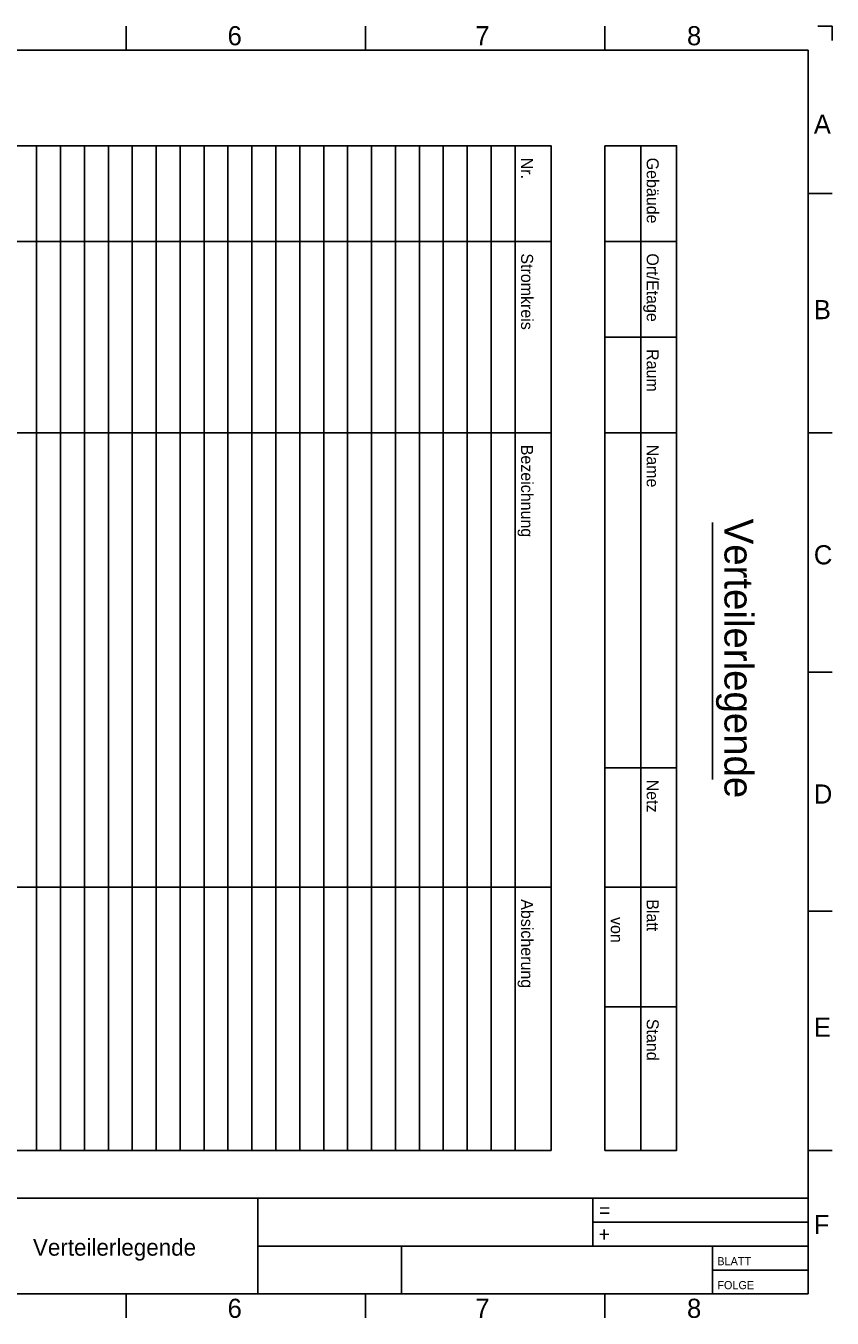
# Model space of a CAD drawing. Extents: x 0 to 395, y 0 to 270.
# Drawn here: x 226.5 to 395, y -0.1 to 270.1 of the extents above; entities that cross this region are included whole.
import ezdxf

# ---------------------------------------------------------------- set-up
doc = ezdxf.new("R2010")
doc.units = 0
for name, color, linetype in [('30_Graphik', 7, 'Continuous'), ('30_Text', 7, 'Continuous'), ('90_Plankopf', 7, 'Continuous')]:
    doc.layers.add(name, color=color, linetype=linetype)

msp = doc.modelspace()

# ---------------------------------------------------------------- linework, layer by layer
at = {"layer": '30_Graphik'}
msp.add_line((370, 166.25), (370, 112.5), dxfattribs=at)
for points in [[(223.75, 245), (223.75, 225), (228.75, 225), (228.75, 245)], [(228.75, 245), (228.75, 225), (233.75, 225), (233.75, 245)], [(233.75, 245), (233.75, 225), (238.75, 225), (238.75, 245)], [(238.75, 245), (238.75, 225), (243.75, 225), (243.75, 245)], [(243.75, 245), (243.75, 225), (248.75, 225), (248.75, 245)], [(248.75, 245), (248.75, 225), (253.75, 225), (253.75, 245)], [(253.75, 245), (253.75, 225), (258.75, 225), (258.75, 245)], [(258.75, 245), (258.75, 225), (263.75, 225), (263.75, 245)], [(263.75, 245), (263.75, 225), (268.75, 225), (268.75, 245)], [(268.75, 245), (268.75, 225), (273.75, 225), (273.75, 245)], [(273.75, 245), (273.75, 225), (278.75, 225), (278.75, 245)], [(278.75, 245), (278.75, 225), (283.75, 225), (283.75, 245)], [(283.75, 245), (283.75, 225), (288.75, 225), (288.75, 245)], [(288.75, 245), (288.75, 225), (293.75, 225), (293.75, 245)], [(293.75, 245), (293.75, 225), (298.75, 225), (298.75, 245)], [(298.75, 245), (298.75, 225), (303.75, 225), (303.75, 245)], [(303.75, 245), (303.75, 225), (308.75, 225), (308.75, 245)], [(308.75, 245), (308.75, 225), (313.75, 225), (313.75, 245)], [(313.75, 245), (313.75, 225), (318.75, 225), (318.75, 245)], [(318.75, 245), (318.75, 225), (323.75, 225), (323.75, 245)], [(323.75, 245), (323.75, 225), (328.75, 225), (328.75, 245)], [(328.75, 245), (328.75, 225), (336.25, 225), (336.25, 245)], [(347.5, 245), (347.5, 225), (355, 225), (355, 245)], [(355, 245), (355, 225), (362.5, 225), (362.5, 245)], [(223.75, 225), (223.75, 185), (228.75, 185), (228.75, 225)], [(228.75, 225), (228.75, 185), (233.75, 185), (233.75, 225)], [(233.75, 225), (233.75, 185), (238.75, 185), (238.75, 225)], [(238.75, 225), (238.75, 185), (243.75, 185), (243.75, 225)], [(243.75, 225), (243.75, 185), (248.75, 185), (248.75, 225)], [(248.75, 225), (248.75, 185), (253.75, 185), (253.75, 225)], [(253.75, 225), (253.75, 185), (258.75, 185), (258.75, 225)], [(258.75, 225), (258.75, 185), (263.75, 185), (263.75, 225)], [(263.75, 225), (263.75, 185), (268.75, 185), (268.75, 225)], [(268.75, 225), (268.75, 185), (273.75, 185), (273.75, 225)], [(273.75, 225), (273.75, 185), (278.75, 185), (278.75, 225)], [(278.75, 225), (278.75, 185), (283.75, 185), (283.75, 225)], [(283.75, 225), (283.75, 185), (288.75, 185), (288.75, 225)], [(288.75, 225), (288.75, 185), (293.75, 185), (293.75, 225)], [(293.75, 225), (293.75, 185), (298.75, 185), (298.75, 225)], [(298.75, 225), (298.75, 185), (303.75, 185), (303.75, 225)], [(303.75, 225), (303.75, 185), (308.75, 185), (308.75, 225)], [(308.75, 225), (308.75, 185), (313.75, 185), (313.75, 225)], [(313.75, 225), (313.75, 185), (318.75, 185), (318.75, 225)], [(318.75, 225), (318.75, 185), (323.75, 185), (323.75, 225)], [(323.75, 225), (323.75, 185), (328.75, 185), (328.75, 225)], [(328.75, 225), (328.75, 185), (336.25, 185), (336.25, 225)], [(347.5, 225), (347.5, 205), (355, 205), (355, 225)], [(355, 225), (355, 205), (362.5, 205), (362.5, 225)], [(347.5, 205), (347.5, 185), (355, 185), (355, 205)], [(355, 205), (355, 185), (362.5, 185), (362.5, 205)], [(223.75, 185), (223.75, 90), (228.75, 90), (228.75, 185)], [(228.75, 185), (228.75, 90), (233.75, 90), (233.75, 185)], [(233.75, 185), (233.75, 90), (238.75, 90), (238.75, 185)], [(238.75, 185), (238.75, 90), (243.75, 90), (243.75, 185)], [(243.75, 185), (243.75, 90), (248.75, 90), (248.75, 185)], [(248.75, 185), (248.75, 90), (253.75, 90), (253.75, 185)], [(253.75, 185), (253.75, 90), (258.75, 90), (258.75, 185)], [(258.75, 185), (258.75, 90), (263.75, 90), (263.75, 185)], [(263.75, 185), (263.75, 90), (268.75, 90), (268.75, 185)], [(268.75, 185), (268.75, 90), (273.75, 90), (273.75, 185)], [(273.75, 185), (273.75, 90), (278.75, 90), (278.75, 185)], [(278.75, 185), (278.75, 90), (283.75, 90), (283.75, 185)], [(283.75, 185), (283.75, 90), (288.75, 90), (288.75, 185)], [(288.75, 185), (288.75, 90), (293.75, 90), (293.75, 185)], [(293.75, 185), (293.75, 90), (298.75, 90), (298.75, 185)], [(298.75, 185), (298.75, 90), (303.75, 90), (303.75, 185)], [(303.75, 185), (303.75, 90), (308.75, 90), (308.75, 185)], [(308.75, 185), (308.75, 90), (313.75, 90), (313.75, 185)], [(313.75, 185), (313.75, 90), (318.75, 90), (318.75, 185)], [(318.75, 185), (318.75, 90), (323.75, 90), (323.75, 185)], [(323.75, 185), (323.75, 90), (328.75, 90), (328.75, 185)], [(328.75, 185), (328.75, 90), (336.25, 90), (336.25, 185)], [(347.5, 185), (347.5, 115), (355, 115), (355, 185)], [(355, 185), (355, 115), (362.5, 115), (362.5, 185)], [(347.5, 115), (347.5, 90), (355, 90), (355, 115)], [(355, 115), (355, 90), (362.5, 90), (362.5, 115)], [(223.75, 90), (223.75, 35), (228.75, 35), (228.75, 90)], [(228.75, 90), (228.75, 35), (233.75, 35), (233.75, 90)], [(233.75, 90), (233.75, 35), (238.75, 35), (238.75, 90)], [(238.75, 90), (238.75, 35), (243.75, 35), (243.75, 90)], [(243.75, 90), (243.75, 35), (248.75, 35), (248.75, 90)], [(248.75, 90), (248.75, 35), (253.75, 35), (253.75, 90)], [(253.75, 90), (253.75, 35), (258.75, 35), (258.75, 90)], [(258.75, 90), (258.75, 35), (263.75, 35), (263.75, 90)], [(263.75, 90), (263.75, 35), (268.75, 35), (268.75, 90)], [(268.75, 90), (268.75, 35), (273.75, 35), (273.75, 90)], [(273.75, 90), (273.75, 35), (278.75, 35), (278.75, 90)], [(278.75, 90), (278.75, 35), (283.75, 35), (283.75, 90)], [(283.75, 90), (283.75, 35), (288.75, 35), (288.75, 90)], [(288.75, 90), (288.75, 35), (293.75, 35), (293.75, 90)], [(293.75, 90), (293.75, 35), (298.75, 35), (298.75, 90)], [(298.75, 90), (298.75, 35), (303.75, 35), (303.75, 90)], [(303.75, 90), (303.75, 35), (308.75, 35), (308.75, 90)], [(308.75, 90), (308.75, 35), (313.75, 35), (313.75, 90)], [(313.75, 90), (313.75, 35), (318.75, 35), (318.75, 90)], [(318.75, 90), (318.75, 35), (323.75, 35), (323.75, 90)], [(323.75, 90), (323.75, 35), (328.75, 35), (328.75, 90)], [(328.75, 90), (328.75, 35), (336.25, 35), (336.25, 90)], [(347.5, 90), (347.5, 65), (355, 65), (355, 90)], [(355, 90), (355, 65), (362.5, 65), (362.5, 90)], [(347.5, 65), (347.5, 35), (355, 35), (355, 65)], [(355, 65), (355, 35), (362.5, 35), (362.5, 65)]]:
    msp.add_lwpolyline(points, close=True, dxfattribs=at)
at = {"layer": '90_Plankopf'}
for p, q in [((247.5, 270), (247.5, 265)), ((297.5, 270), (297.5, 265)), ((347.5, 270), (347.5, 265)), ((395, 270), (392, 270)), ((395, 270), (395, 267)), ((390, 265), (5, 265)), ((390, 5), (390, 265)), ((390, 235), (395, 235)), ((390, 185), (395, 185)), ((390, 135), (395, 135)), ((390, 85), (395, 85)), ((390, 35), (395, 35)), ((5, 25), (390, 25)), ((275, 5), (275, 25)), ((345, 15), (345, 25)), ((345, 20), (390, 20)), ((275, 15), (390, 15)), ((305, 5), (305, 15)), ((370, 15), (370, 5)), ((370, 10), (390, 10)), ((5, 5), (390, 5)), ((247.5, 5), (247.5, 0)), ((297.5, 5), (297.5, 0)), ((347.5, 5), (347.5, 0))]:
    msp.add_line(p, q, dxfattribs=at)

# ---------------------------------------------------------------- texts
at = {"layer": '30_Text'}
for s, height, p in [('Nr.', 2.5, (330, 242.5)), ('Gebäude', 2.5, (356.25, 242.5)), ('Stromkreis', 2.5, (330, 222.5)), ('Ort/Etage', 2.5, (356.25, 222.5)), ('Raum', 2.5, (356.25, 202.5)), ('Bezeichnung', 2.5, (330, 182.5)), ('Name', 2.5, (356.25, 182.5)), ('Verteilerlegende', 6, (372.5, 167.05)), ('Netz', 2.5, (356.25, 112.5)), ('Absicherung', 2.5, (330, 87.5)), ('Blatt', 2.5, (356.25, 87.5)), ('    von    ', 2.5, (348.75, 87.5)), ('Stand', 2.5, (356.25, 62.5))]:
    msp.add_text(s, height=height, rotation=270, dxfattribs=at).set_placement(p)
at = {"layer": '90_Plankopf'}
for s, height, p in [('6', 4, (268.67, 266)), ('7', 4, (320.42, 266)), ('8', 4, (364.67, 266)), ('A', 4, (391.17, 247.5)), ('B', 4, (391.17, 208.75)), ('C', 4, (391.17, 157.5)), ('D', 4, (391.17, 107.5)), ('E', 4, (391.17, 58.75)), ('=', 3, (346.26, 21)), ('F', 4, (391.17, 17.5)), ('Verteilerlegende    ', 3.5, (228, 13)), ('+', 3, (346.19, 16)), ('BLATT', 1.7, (371, 11)), ('FOLGE', 1.7, (371, 6)), ('6', 4, (268.67, 0)), ('7', 4, (320.42, 0)), ('8', 4, (364.67, 0))]:
    msp.add_text(s, height=height, dxfattribs=at).set_placement(p)

doc.saveas('drawing.dxf')
